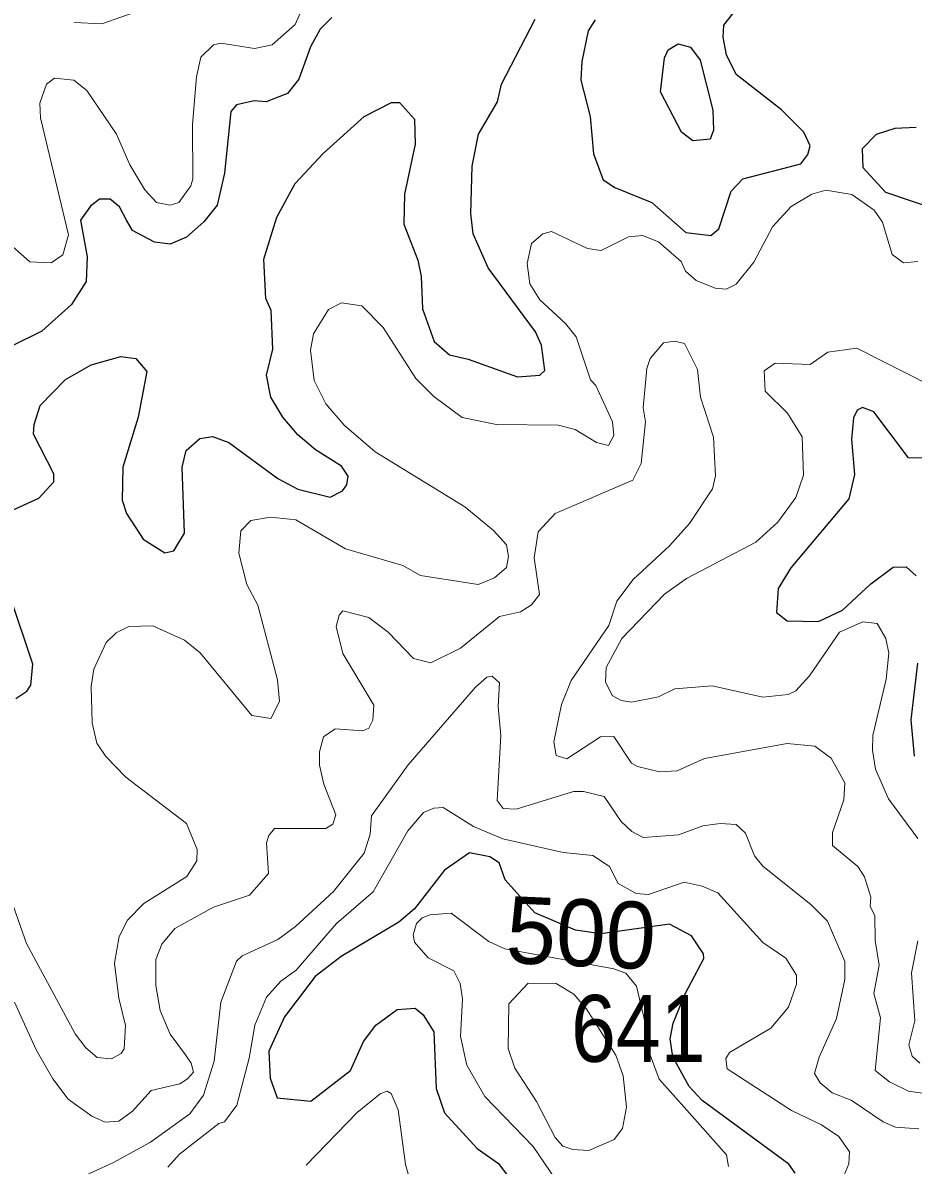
# Model space of a CAD drawing. Extents: x 763.2 to 816.8, y 7896.5 to 7952.7.
# Drawn here: x 797.936 to 800.064, y 7915.025 to 7917.757 of the extents above; entities that cross this region are included whole.
import ezdxf
from ezdxf.enums import TextEntityAlignment as Align

# ---------------------------------------------------------------- set-up
doc = ezdxf.new("R2010")
doc.units = 0
doc.header["$LTSCALE"] = 0.064
doc.layers.add('1', color=7, linetype='Continuous', lineweight=25)
doc.layers.add('2', color=7, linetype='Continuous', lineweight=13)
doc.layers.add('21', color=7, linetype='Continuous')
doc.layers.add('61', color=7, linetype='Continuous')

msp = doc.modelspace()

# ---------------------------------------------------------------- linework, layer by layer
at = {"layer": '1'}
for points in [[(799.3039, 7917.7638), (799.2874, 7917.7379), (799.272, 7917.6643), (799.2698, 7917.6199), (799.2927, 7917.5326), (799.3004, 7917.4438), (799.3231, 7917.3811), (799.3511, 7917.3631), (799.44, 7917.3275), (799.5213, 7917.2552), (799.5806, 7917.2479), (799.5999, 7917.2645), (799.6296, 7917.3544), (799.6571, 7917.3841), (799.7961, 7917.4199), (799.8125, 7917.4421), (799.8183, 7917.4626), (799.8033, 7917.4954), (799.7496, 7917.549), (799.6414, 7917.6331), (799.6183, 7917.6806), (799.6102, 7917.7226), (799.6122, 7917.7516), (799.6531, 7917.8039)], [(798.675, 7917.7692), (798.647, 7917.7413), (798.6239, 7917.6994), (798.5961, 7917.6222), (798.5684, 7917.5876), (798.5175, 7917.568), (798.4891, 7917.5701), (798.447, 7917.5606), (798.4333, 7917.5449), (798.4183, 7917.3971), (798.4009, 7917.3207), (798.3691, 7917.2812), (798.327, 7917.2439), (798.2886, 7917.2272)], [(798.9195, 7916.9944), (798.9558, 7916.9627), (799.0003, 7916.9524), (799.1187, 7916.9099), (799.1722, 7916.9141), (799.1837, 7916.9258), (799.1758, 7916.9859), (799.1616, 7917.0176), (799.0484, 7917.1709), (799.0123, 7917.2525), (799.0068, 7917.3011), (799.0106, 7917.4142), (799.0253, 7917.4905), (799.0705, 7917.5682), (799.08, 7917.6098), (799.161, 7917.7653)], [(797.9026, 7916.5875), (797.974, 7916.6202), (798.0105, 7916.6594), (798.0104, 7916.6783), (797.962, 7916.7728), (797.9633, 7916.7964), (797.9778, 7916.8418), (798.0379, 7916.9036), (798.0991, 7916.939), (798.1707, 7916.9589), (798.2064, 7916.9543), (798.2323, 7916.9228), (798.2116, 7916.8137), (798.1754, 7916.6945), (798.1737, 7916.615), (798.184, 7916.5832), (798.2235, 7916.5218), (798.2756, 7916.4894), (798.2968, 7916.4942), (798.3227, 7916.5361), (798.3166, 7916.6945), (798.3269, 7916.7344), (798.3594, 7916.7632), (798.3897, 7916.768), (798.4283, 7916.7535), (798.546, 7916.667), (798.5935, 7916.6416), (798.6708, 7916.6224), (798.7002, 7916.6376), (798.7108, 7916.6518), (798.7139, 7916.6726), (798.6979, 7916.697), (798.6355, 7916.7356), (798.5933, 7916.7712), (798.5578, 7916.8135), (798.5293, 7916.8619), (798.5188, 7916.9141), (798.5334, 7916.9764), (798.53, 7917.0693), (798.5169, 7917.0973), (798.5126, 7917.1916), (798.5431, 7917.292), (798.5873, 7917.373), (798.6537, 7917.4441), (798.7522, 7917.5325), (798.8173, 7917.5662), (798.8367, 7917.5663), (798.8721, 7917.5262), (798.8737, 7917.4669), (798.8488, 7917.3468)], [(800.072, 7917.5069), (800.0207, 7917.5041), (799.9761, 7917.4894), (799.9426, 7917.4559), (799.9441, 7917.4105), (799.998, 7917.352), (800.173, 7917.2929)], [(798.1448, 7917.3351), (798.119, 7917.3351), (798.0977, 7917.3182), (798.0737, 7917.2853), (798.0896, 7917.1974), (798.0879, 7917.1383), (798.0524, 7917.083), (797.9813, 7917.0195), (797.9087, 7916.9839)], [(798.2886, 7917.2272), (798.251, 7917.2321), (798.198, 7917.2606), (798.1842, 7917.2853), (798.1675, 7917.3171), (798.1448, 7917.3351)], [(798.8488, 7917.3468), (798.8469, 7917.2751), (798.8807, 7917.1891), (798.8885, 7917.1506), (798.8917, 7917.0732), (798.9195, 7916.9944)], [(799.9307, 7916.8306), (799.9222, 7916.812), (799.9174, 7916.761), (799.9239, 7916.6764), (799.9104, 7916.6189), (799.7722, 7916.4538)], [(800.1209, 7916.716), (800.0533, 7916.7165), (799.9704, 7916.8268), (799.9437, 7916.837), (799.9307, 7916.8306)], [(799.7722, 7916.4538), (799.7414, 7916.4044), (799.7378, 7916.3467), (799.7631, 7916.3265), (799.8384, 7916.3249), (799.8959, 7916.3527), (799.9634, 7916.4151), (800.0169, 7916.4551), (800.0479, 7916.456), (800.0714, 7916.4346)], [(797.9194, 7916.1409), (797.946, 7916.1586), (797.9555, 7916.1732), (797.9598, 7916.2235), (797.906, 7916.3848)], [(800.075, 7916.2252), (800.0587, 7916.0897), (800.0666, 7916.0028)], [(799.7824, 7915.006), (799.7676, 7915.0279), (799.5601, 7915.1798), (799.5292, 7915.2133), (799.4896, 7915.2844), (799.4836, 7915.3271), (799.4906, 7915.365), (799.5193, 7915.4349), (799.564, 7915.519), (799.5632, 7915.5305), (799.5342, 7915.5735), (799.4816, 7915.6013), (799.3182, 7915.5787), (799.2571, 7915.587), (799.1601, 7915.6287), (799.0892, 7915.7071), (799.075, 7915.7481), (799.0521, 7915.7628), (799.0036, 7915.7723), (798.9441, 7915.7306), (798.872, 7915.6378), (798.8353, 7915.6061), (798.6973, 7915.5239), (798.635, 7915.476), (798.5616, 7915.3797), (798.5238, 7915.2976), (798.5275, 7915.2335), (798.5437, 7915.186), (798.6245, 7915.1781), (798.719, 7915.2516), (798.7508, 7915.3209), (798.7803, 7915.3596), (798.8311, 7915.3976), (798.8743, 7915.4005), (798.893, 7915.3848), (798.9185, 7915.3439), (798.9243, 7915.2086), (798.9442, 7915.1505), (799.0221, 7915.0652), (799.073, 7915.0291), (799.1145, 7914.9734)]]:
    msp.add_lwpolyline(points, dxfattribs=at)
msp.add_lwpolyline([(799.4698, 7917.6728), (799.4788, 7917.6919), (799.5023, 7917.7065), (799.5322, 7917.6988), (799.5555, 7917.6673), (799.5853, 7917.5483), (799.5869, 7917.5005), (799.5795, 7917.4785), (799.538, 7917.4745), (799.511, 7917.4956), (799.4607, 7917.5919)], close=True, dxfattribs=at)
at = {"layer": '2'}
for points in [[(798.3087, 7917.8198), (798.1251, 7917.7546), (798.0589, 7917.758)], [(798.3414, 7917.5134), (798.3512, 7917.6279), (798.362, 7917.6751), (798.3917, 7917.7046), (798.4093, 7917.7084), (798.4902, 7917.6954), (798.532, 7917.7041), (798.5868, 7917.7525), (798.6158, 7917.8186)], [(797.862, 7917.2647), (797.9527, 7917.1856), (798.0035, 7917.1826), (798.0319, 7917.2024), (798.0452, 7917.2498), (797.9781, 7917.53), (797.9769, 7917.5649), (797.9927, 7917.6098), (798.0117, 7917.6245), (798.0583, 7917.6196), (798.0893, 7917.5952), (798.16, 7917.4905), (798.1921, 7917.417), (798.2281, 7917.3578), (798.2553, 7917.327)], [(798.2553, 7917.327), (798.2885, 7917.3206), (798.3092, 7917.3272), (798.3378, 7917.3668), (798.3427, 7917.3841), (798.3414, 7917.5134)], [(800.0757, 7917.1863), (800.0414, 7917.1832), (800.0143, 7917.2029), (799.9909, 7917.2798), (799.9715, 7917.309), (799.9176, 7917.3465), (799.8555, 7917.3565), (799.822, 7917.3469), (799.7729, 7917.3176), (799.728, 7917.269), (799.6838, 7917.1843), (799.6415, 7917.1322), (799.6176, 7917.1202), (799.5908, 7917.1221), (799.5454, 7917.1408), (799.5199, 7917.1633), (799.5097, 7917.1859), (799.456, 7917.233), (799.4175, 7917.2481), (799.3843, 7917.2448), (799.3185, 7917.2122), (799.2863, 7917.2171), (799.2002, 7917.2579), (799.1788, 7917.2522), (799.1523, 7917.2294), (799.1417, 7917.1816), (799.148, 7917.1323), (799.1719, 7917.0941), (799.2336, 7917.0378), (799.2585, 7917.006), (799.2935, 7916.9034), (799.3061, 7916.8892), (799.3455, 7916.8023), (799.3486, 7916.7702), (799.3363, 7916.7457), (799.3072, 7916.7531), (799.2566, 7916.7847), (799.2158, 7916.795), (799.0687, 7916.7964), (798.9865, 7916.8131), (798.9187, 7916.8633), (798.8754, 7916.9064), (798.7973, 7917.0285), (798.7464, 7917.0797), (798.6981, 7917.0871), (798.6665, 7917.0716), (798.6307, 7917.0133), (798.624, 7916.9737), (798.6322, 7916.9016), (798.6602, 7916.8455), (798.7043, 7916.795), (798.7785, 7916.7307), (798.9931, 7916.5995), (799.0616, 7916.5427), (799.0921, 7916.5082), (799.097, 7916.4809), (799.0925, 7916.454), (799.0635, 7916.4293), (799.0247, 7916.4137), (798.8867, 7916.4351), (798.8441, 7916.4594), (798.7071, 7916.4992), (798.5888, 7916.568), (798.5281, 7916.5746), (798.4815, 7916.5665), (798.4576, 7916.542), (798.4525, 7916.4885), (798.4716, 7916.4138), (798.4976, 7916.3644), (798.5449, 7916.1857), (798.5495, 7916.1336), (798.5289, 7916.093), (798.4835, 7916.1005), (798.3598, 7916.2501), (798.3227, 7916.2806), (798.247, 7916.3148), (798.1896, 7916.3134), (798.1591, 7916.298), (798.1356, 7916.2748), (798.1058, 7916.2111), (798.0994, 7916.1695), (798.1015, 7916.0825), (798.1129, 7916.0339), (798.1346, 7916.002), (798.1824, 7915.9527), (798.327, 7915.8425), (798.3527, 7915.78), (798.3524, 7915.753), (798.3284, 7915.7154), (798.2253, 7915.6511), (798.1861, 7915.6109)], [(800.1319, 7915.191), (800.0529, 7915.2024), (800.0081, 7915.2244), (799.9736, 7915.2513), (799.9864, 7915.3772), (799.9701, 7915.4353), (799.9831, 7915.5033), (799.9736, 7915.5627), (799.9732, 7915.6219), (799.9618, 7915.6433), (799.9631, 7915.6657), (799.9483, 7915.7148), (799.9319, 7915.7397), (799.8716, 7915.7892), (799.8717, 7915.8204), (799.8991, 7915.8991), (799.9009, 7915.9391), (799.8686, 7915.9985), (799.8291, 7916.0268), (799.7635, 7916.0338), (799.5657, 7915.9975), (799.4999, 7915.9681), (799.458, 7915.9656), (799.4052, 7915.9781), (799.3912, 7915.9868), (799.3489, 7916.0503), (799.3168, 7916.0491), (799.2364, 7915.9965), (799.211, 7916.0046), (799.2058, 7916.0371), (799.2234, 7916.1267), (799.2466, 7916.1844), (799.3367, 7916.3159), (799.3561, 7916.3735), (799.3952, 7916.4254), (799.4822, 7916.5059), (799.5294, 7916.5597), (799.5851, 7916.6422), (799.592, 7916.6739), (799.5869, 7916.766), (799.5559, 7916.8615), (799.549, 7916.9278), (799.518, 7916.9902), (799.494, 7916.9952), (799.4677, 7916.9918), (799.4354, 7916.9545), (799.4276, 7916.9304), (799.4194, 7916.8359), (799.4242, 7916.8029), (799.4139, 7916.703), (799.3943, 7916.6634), (799.2087, 7916.5834), (799.1682, 7916.5396), (799.1581, 7916.4775), (799.1712, 7916.3899), (799.1524, 7916.3653), (799.1261, 7916.3485), (799.0755, 7916.3374), (798.9822, 7916.2618), (798.9117, 7916.2264), (798.8703, 7916.2365), (798.8095, 7916.2999), (798.7635, 7916.3344), (798.7008, 7916.3504), (798.692, 7916.3406), (798.6848, 7916.3133), (798.7007, 7916.2488), (798.7748, 7916.1253), (798.7731, 7916.0893), (798.7634, 7916.0704), (798.7485, 7916.064), (798.6828, 7916.0684), (798.6551, 7916.0495), (798.6454, 7916.0135), (798.6454, 7915.9813), (798.6554, 7915.9359), (798.6845, 7915.8629), (798.6769, 7915.8403), (798.6603, 7915.8301), (798.5377, 7915.83), (798.5238, 7915.8136), (798.5186, 7915.7956), (798.5236, 7915.7224), (798.478, 7915.6705)], [(800.0753, 7915.8064), (800.0058, 7915.9013), (799.9746, 7915.9724), (799.9669, 7916.0174), (799.9683, 7916.0529), (800, 7916.1872), (800.0059, 7916.2494), (799.9992, 7916.2842), (799.9781, 7916.3208), (799.9439, 7916.3245), (799.888, 7916.2999), (799.817, 7916.195), (799.7842, 7916.1593), (799.7655, 7916.1503), (799.705, 7916.144), (799.584, 7916.1717), (799.4945, 7916.1638), (799.4558, 7916.1451), (799.3908, 7916.1325), (799.3666, 7916.1359), (799.3447, 7916.1483), (799.3291, 7916.1811), (799.3308, 7916.2151), (799.3683, 7916.2847), (799.4704, 7916.3903), (799.5229, 7916.4282), (799.6883, 7916.515), (799.7413, 7916.563), (799.784, 7916.6217), (799.8022, 7916.6754), (799.7991, 7916.7672), (799.7639, 7916.8231), (799.7103, 7916.8759), (799.7079, 7916.9248), (799.7346, 7916.9426), (799.818, 7916.9395), (799.8603, 7916.9696), (799.93, 7916.9787), (800.1041, 7916.8904)], [(799.0758, 7916.1788), (799.0579, 7916.1941), (799.0452, 7916.1917), (799.0184, 7916.1685), (798.8569, 7915.9823), (798.7692, 7915.8606), (798.7667, 7915.8163), (798.7523, 7915.7716), (798.6786, 7915.6794), (798.5881, 7915.5956), (798.5455, 7915.5646), (798.4602, 7915.5255), (798.4469, 7915.5126), (798.4091, 7915.4148), (798.3936, 7915.2739), (798.3676, 7915.1927), (798.3355, 7915.1478), (798.2413, 7915.0798), (798.1529, 7915.0317), (798.0067, 7914.9643), (797.9573, 7914.9623), (797.9061, 7915.0062)], [(799.1153, 7915.8762), (799.0847, 7915.8777), (799.0698, 7915.8972), (799.0791, 7916.0528), (799.0726, 7916.1218), (799.0758, 7916.1788)], [(800.0777, 7915.1119), (800.0221, 7915.1163), (799.9925, 7915.1286), (799.9159, 7915.1804), (799.8708, 7915.1978), (799.8421, 7915.2223), (799.8285, 7915.2441), (799.8396, 7915.283), (799.8809, 7915.3758), (799.901, 7915.4692), (799.901, 7915.512), (799.8597, 7915.6086), (799.8202, 7915.6482), (799.7049, 7915.7401), (799.6854, 7915.765), (799.6633, 7915.8188), (799.641, 7915.8396), (799.6028, 7915.8424), (799.5617, 7915.8364), (799.5032, 7915.8154), (799.4192, 7915.8087), (799.3917, 7915.8227), (799.3663, 7915.8469), (799.3256, 7915.9066), (799.2764, 7915.9187), (799.2523, 7915.9184), (799.1153, 7915.8762)], [(799.8945, 7914.9904), (799.9106, 7915.0281), (799.9121, 7915.0569), (799.8871, 7915.0937), (799.845, 7915.1217), (799.774, 7915.1555), (799.6201, 7915.2555), (799.6166, 7915.2799), (799.6254, 7915.2944), (799.7244, 7915.3531), (799.7668, 7915.4032), (799.7856, 7915.458), (799.7859, 7915.4793), (799.7604, 7915.52), (799.7054, 7915.5573), (799.5975, 7915.6764), (799.5602, 7915.6926), (799.5171, 7915.7016), (799.4315, 7915.6725), (799.4022, 7915.6744), (799.3593, 7915.6985), (799.3386, 7915.7395), (799.2987, 7915.7658), (799.2275, 7915.7726), (799.0838, 7915.8052), (799.0135, 7915.835), (798.9411, 7915.8807), (798.9183, 7915.8791), (798.8939, 7915.8687), (798.8565, 7915.8247), (798.7734, 7915.6788), (798.6859, 7915.6028), (798.5894, 7915.4917), (798.5528, 7915.4648), (798.5185, 7915.4267), (798.491, 7915.36), (798.4775, 7915.2812), (798.4479, 7915.1685), (798.418, 7915.1284), (798.405, 7915.1245), (798.3106, 7915.0514), (798.2825, 7915.0204)], [(798.1785, 7915.3036), (798.171, 7915.2924), (798.1483, 7915.2796), (798.1137, 7915.2829), (798.087, 7915.3054), (798.0611, 7915.3392), (797.9446, 7915.5552), (797.8991, 7915.6847)], [(798.478, 7915.6705), (798.3916, 7915.6423), (798.2992, 7915.5907), (798.2687, 7915.5533), (798.2541, 7915.5167), (798.2542, 7915.4547)], [(799.6232, 7915.022), (799.6184, 7915.05), (799.5168, 7915.1636), (799.4571, 7915.2306), (799.426, 7915.3141), (799.4239, 7915.3653), (799.4027, 7915.453), (799.3776, 7915.4839), (799.3488, 7915.4948), (799.0884, 7915.5427), (799.0504, 7915.5602), (798.9599, 7915.6278), (798.9102, 7915.624), (798.8911, 7915.6166), (798.8773, 7915.6027), (798.8691, 7915.576), (798.8721, 7915.5583), (798.905, 7915.5212), (798.9661, 7915.4902), (798.9814, 7915.4595), (798.9872, 7915.4231), (798.9824, 7915.3331), (798.9972, 7915.2641), (799.0406, 7915.1892), (799.1559, 7915.0696), (799.2103, 7914.9901)], [(798.1861, 7915.6109), (798.1666, 7915.5723), (798.1556, 7915.5079), (798.1657, 7915.4244), (798.1818, 7915.3594), (798.1785, 7915.3036)], [(800.0805, 7915.2689), (800.062, 7915.2859), (800.0537, 7915.3131), (800.0685, 7915.3705), (800.0603, 7915.4849), (800.0754, 7915.5612)], [(798.2542, 7915.4547), (798.2642, 7915.3953), (798.2882, 7915.3384), (798.3252, 7915.2887), (798.3385, 7915.2693), (798.3439, 7915.2477), (798.3295, 7915.2315), (798.3117, 7915.2199), (798.2431, 7915.2039), (798.1983, 7915.1546), (798.1656, 7915.1302), (798.1326, 7915.1283), (798.1011, 7915.1423), (798.0446, 7915.1833), (798.0078, 7915.2319), (797.9683, 7915.3009), (797.9161, 7915.4146)], [(798.6132, 7915.0251), (798.7352, 7915.1508), (798.79, 7915.1955), (798.8071, 7915.2022), (798.8164, 7915.1965), (798.8331, 7915.1574), (798.8511, 7915.0266), (798.8783, 7914.9308)]]:
    msp.add_lwpolyline(points, dxfattribs=at)
msp.add_lwpolyline([(799.2826, 7915.3998), (799.2533, 7915.4339), (799.2112, 7915.4598), (799.1438, 7915.4601), (799.0975, 7915.4107), (799.0962, 7915.3043), (799.1122, 7915.2568), (799.1639, 7915.1771), (799.2084, 7915.0916), (799.2269, 7915.0705), (799.2506, 7915.0623), (799.2895, 7915.0603), (799.3498, 7915.0863), (799.3698, 7915.1125), (799.3794, 7915.1641), (799.3715, 7915.2386), (799.3533, 7915.2883)], close=True, dxfattribs=at)

# ---------------------------------------------------------------- texts
at = {"layer": '21', "width": 0.9}
msp.add_text('641', height=0.16, dxfattribs=at).set_placement((799.2467, 7915.2722))
at = {"layer": '61'}
msp.add_text('500', height=0.16, rotation=357.402, dxfattribs=at).set_placement((799.267, 7915.501), align=Align.CENTER)

doc.saveas('drawing.dxf')
